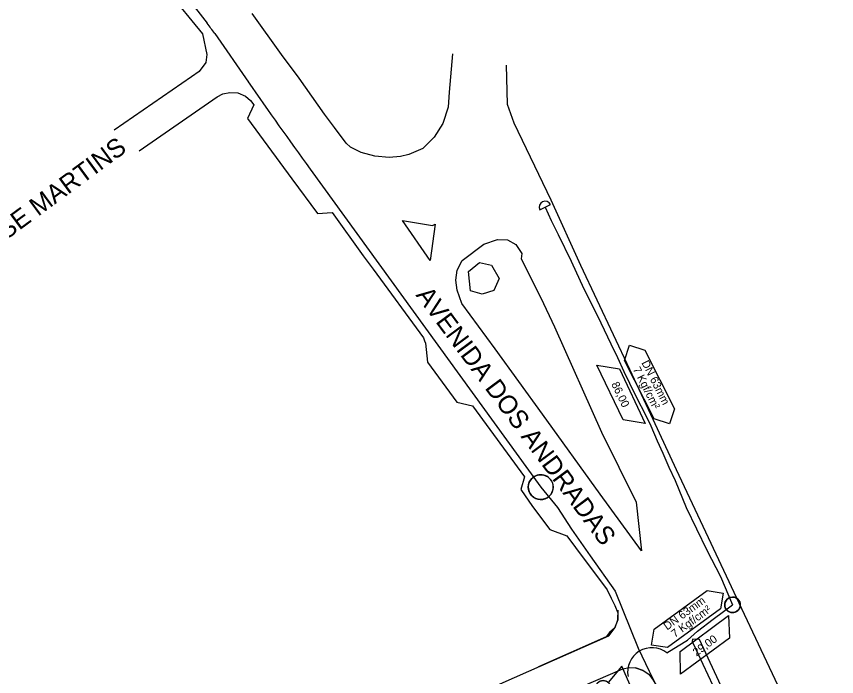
# Model space of a CAD drawing. Extents: x 656692 to 673945, y 7585994 to 7599066.
# Drawn here: x 669344.7 to 669663.5, y 7595890.6 to 7596147.3 of the extents above; entities that cross this region are included whole.
import ezdxf

# ---------------------------------------------------------------- set-up
doc = ezdxf.new("R2010")
doc.units = 0
for name, color, linetype in [('LOGRADOURO', 7, 'Continuous'), ('LOGRADOURO_TEXTO', 7, 'Continuous'), ('MEIO FIO', 7, 'Continuous'), ('SIMBOLO', 7, 'Continuous'), ('TEXTO', 7, 'Continuous'), ('TUBO_PEAD_GN_125', 7, 'Continuous'), ('TUBO_PEAD_GN_63', 7, 'Continuous'), ('VALVULA_PEAD_63', 7, 'Continuous')]:
    doc.layers.add(name, color=color, linetype=linetype)

# ---------------------------------------------------------------- blocks, each defined once
blk = doc.blocks.new('INTERLIGACAO_9')
at = {"layer": 'SIMBOLO'}
blk.add_circle((0, 0), 4.19, dxfattribs=at)
for start, end in [(0, 180), (180, 0)]:
    blk.add_arc((0, 0), 4.19, start, end, dxfattribs=at)
blk = doc.blocks.new('VALVULA_PEAD_DN_16')
at = {"layer": 'VALVULA_PEAD_63'}
for points in [[(-0.0374, 0.0187), (-0.1395, 0.0698), (-0.1395, -0.0698), (-0.0374, -0.0187)], [(-0.0374, -0.0187), (-0.1395, -0.0698), (-0.1395, 0.0698), (-0.0374, 0.0187)], [(0.0374, -0.0187), (0.1395, -0.0698), (0.1395, 0.0698), (0.0374, 0.0187)], [(0.0374, -0.0187), (0.1395, -0.0698), (0.1395, 0.0698), (0.0374, 0.0187)]]:
    blk.add_lwpolyline(points, dxfattribs=at)
blk.add_circle((0, 0), 0.0419, dxfattribs=at)
for start, end in [(90, 270), (153.4349, 206.5651), (270, 90), (333.4349, 26.5651)]:
    blk.add_arc((0, 0), 0.0419, start, end, dxfattribs=at)
blk = doc.blocks.new('INTERLIGACAO_12')
at = {"layer": 'SIMBOLO'}
blk.add_circle((0, 0), 4.19, dxfattribs=at)
for start, end in [(0, 180), (180, 0)]:
    blk.add_arc((0, 0), 4.19, start, end, dxfattribs=at)

msp = doc.modelspace()

# ---------------------------------------------------------------- linework, layer by layer
at = {"layer": 'LOGRADOURO'}
msp.add_line((669588.36, 7595892.97), (669585.35, 7595894.02), dxfattribs=at)
for points in [[(669403.4, 7596157.23), (669416.98, 7596140.49), (669418.75, 7596132.42), (669418.35, 7596129.3), (669415.73, 7596125.88), (669412.71, 7596123.73), (669382.74, 7596102.97)], [(669514.24, 7596132.7), (669512.92, 7596117.74), (669512.56, 7596111.95), (669510.49, 7596105.58), (669507.03, 7596100.34), (669502.7, 7596095.96), (669497.23, 7596093.53), (669494.06, 7596092.8), (669489.66, 7596092.37), (669484.06, 7596092.87), (669478.77, 7596094.33), (669474.63, 7596096.47), (669472.92, 7596098.02), (669468.37, 7596104.02), (669464.44, 7596109.21), (669454.67, 7596123.26), (669447.71, 7596132.4), (669436.32, 7596148.42)], [(669535.04, 7596128.35), (669535.5, 7596113.18), (669538, 7596105.82), (669552.44, 7596075.95), (669564.02, 7596050.57), (669582.96, 7596010.06), (669592.14, 7595990.61), (669601.2, 7595971.12), (669613.6, 7595944.63), (669626.5, 7595917.1), (669642.76, 7595882.69)], [(669392.44, 7596095.01), (669422.69, 7596116.02), (669424.99, 7596117.2), (669427.63, 7596117.73), (669430.74, 7596117.48), (669433.8, 7596116.26), (669435.71, 7596114.53), (669436.94, 7596112.83), (669434.56, 7596107.61), (669451.82, 7596084.16), (669461.78, 7596070.56), (669467.47, 7596071.04), (669479.52, 7596054.19), (669483.37, 7596049), (669502.91, 7596022.26), (669503.37, 7596021.1), (669503.73, 7596020.16), (669504.5, 7596012.81), (669515.96, 7595997.29), (669521.95, 7595995.87), (669542.18, 7595968.2), (669540.78, 7595963.27), (669545.35, 7595956.74), (669552.02, 7595947.8), (669558.7, 7595945.31), (669562.04, 7595940.74), (669574.36, 7595924.25), (669575.86, 7595921.11), (669577.33, 7595918.21), (669578.54, 7595915.31), (669578.46, 7595912.59), (669577.23, 7595909.39), (669575.24, 7595907.72), (669573.97, 7595905.98), (669547.68, 7595894.4)], [(669321.54, 7595794.23), (669359.27, 7595810.97), (669367.95, 7595814.75), (669399.74, 7595828.85), (669417.79, 7595836.75), (669442.46, 7595847.64), (669450.75, 7595844.67), (669458.2, 7595847.94), (669465.54, 7595851.19), (669466.64, 7595858.35), (669468.76, 7595859.3), (669477.05, 7595862.95), (669507.28, 7595876.53), (669538.25, 7595890.25), (669575.02, 7595906.45), (669577.47, 7595909.7), (669578.46, 7595912.59), (669578.58, 7595916.4)], [(669553.79, 7595882.06), (669580.42, 7595893.61), (669582.82, 7595894.1), (669585.35, 7595894.02), (669588.34, 7595892.98), (669590.53, 7595891.47), (669592.25, 7595889.23), (669594.49, 7595885.22), (669611.97, 7595846.58), (669622.46, 7595823.54), (669633.74, 7595799.1), (669648.11, 7595768.42), (669649.11, 7595765.62), (669649.81, 7595762.99), (669649.9, 7595759.85), (669649.5, 7595757.16), (669648.42, 7595754.65), (669646.35, 7595751.78), (669644.89, 7595750.78), (669637.86, 7595747.18), (669632.34, 7595749.1), (669607.54, 7595737.68)]]:
    msp.add_lwpolyline(points, dxfattribs=at)
for points in [[(669531.69, 7596060.54), (669535.62, 7596060.32), (669538.88, 7596058.51), (669541.16, 7596055.01), (669540.94, 7596053.01), (669548.49, 7596037.81), (669553.83, 7596026.5), (669572.14, 7595985.59), (669585.66, 7595958.43), (669587.64, 7595939.52), (669571.56, 7595961.47), (669549.19, 7595992.6), (669530.85, 7596017.95), (669517.88, 7596035.69), (669516.08, 7596040.83), (669515.51, 7596044.68), (669516.04, 7596048.65), (669518.01, 7596052.4), (669526.33, 7596058.74)], [(669521.16, 7596040.51), (669520.43, 7596048.09), (669524.74, 7596051.57), (669529.31, 7596050.53), (669532.32, 7596045.33), (669530.32, 7596040.73), (669525.72, 7596039.21)], [(669607.45, 7595905.13), (669607.4, 7595904.23), (669607.57, 7595903.69), (669619.3, 7595878.82), (669646.8, 7595819.29), (669647.05, 7595819.15), (669660.73, 7595789.07), (669663.51, 7595790.14), (669649.55, 7595820.32), (669621.14, 7595881.57), (669610.2, 7595905.02)]]:
    msp.add_lwpolyline(points, close=True, dxfattribs=at)
at = {"layer": 'MEIO FIO'}
msp.add_lwpolyline([(669506.49, 7596065.93), (669507.48, 7596066.45), (669505.51, 7596052.33), (669494.81, 7596067.85)], close=True, dxfattribs=at)
at = {"layer": 'SIMBOLO'}
for points in [[(669582.99, 7596019.46), (669588.93, 7596017.51), (669600.46, 7595994.73), (669598.51, 7595988.78), (669592.57, 7595990.73), (669581.04, 7596013.52), (669582.99, 7596019.46)], [(669591.59, 7595902.82), (669592.57, 7595909), (669613.22, 7595924.02), (669619.4, 7595923.04), (669618.43, 7595916.86), (669597.77, 7595901.84), (669591.59, 7595902.82)]]:
    msp.add_lwpolyline(points, dxfattribs=at)
at = {"layer": 'TEXTO'}
for points in [[(669579.06, 7596010.21), (669589.16, 7595988.99), (669580.51, 7595990.34), (669570.34, 7596011.69), (669579.06, 7596010.21)], [(669602.64, 7595900.34), (669621.55, 7595914.3), (669621.87, 7595905.55), (669602.84, 7595891.5), (669602.64, 7595900.34)]]:
    msp.add_lwpolyline(points, dxfattribs=at)
at = {"layer": 'TUBO_PEAD_GN_125'}
for p, q in [((669395.93, 7596174.39), (669418.86, 7596144.6)), ((669421.78, 7596140.6), (669434.86, 7596121.75)), ((669458.87, 7596087.89), (669548.51, 7595964.23))]:
    msp.add_line(p, q, dxfattribs=at)
msp.add_lwpolyline([(669548.51, 7595964.23), (669555.08, 7595956.26), (669560.48, 7595947.9), (669567.69, 7595937.57), (669577.47, 7595923.79), (669586.34, 7595901.62), (669590.7, 7595892.69), (669596.78, 7595880.52)], dxfattribs=at)
for centre, radius, start, end in [((669339.51, 7596083.53), 100.12, 34.7502, 37.5824), ((671080.16, 7597263.15), 2002.45, 214.75024, 215.9378)]:
    msp.add_arc(centre, radius, start, end, dxfattribs=at)
at = {"layer": 'TUBO_PEAD_GN_63'}
msp.add_line((669548.18, 7596072.05), (669552.32, 7596074.09), dxfattribs=at)
for points in [[(669550.25, 7596073.07), (669552.51, 7596067.84), (669555.34, 7596062.43), (669560.34, 7596052.06), (669565.27, 7596041.36), (669570.53, 7596030.77), (669573.16, 7596025.35), (669575.75, 7596019.99), (669578.33, 7596014.64), (669580.86, 7596009.25), (669583.07, 7596004.63), (669585.82, 7595998.78), (669589.08, 7595992.57), (669591.32, 7595988.02), (669593.72, 7595982.25), (669595.97, 7595977.38), (669598.31, 7595972.01), (669600.7, 7595966.76), (669605.1, 7595956.31), (669613.04, 7595939.78), (669618.36, 7595929.47), (669623.05, 7595918.47)], [(669597.57, 7595899.82), (669601.87, 7595902.47), (669605.56, 7595904.74), (669609.47, 7595908.17), (669615.54, 7595912.91), (669623.05, 7595918.47)]]:
    msp.add_lwpolyline(points, dxfattribs=at)
for centre, radius, start, end in [((669550.25, 7596073.07), 2.31, 26.2909, 206.1425), ((669591.75, 7595892.33), 9.48, 52.1284, 190.7931)]:
    msp.add_arc(centre, radius, start, end, dxfattribs=at)

# ---------------------------------------------------------------- block references
at = {"layer": 'SIMBOLO'}
for name, p, xscale, yscale, rotation in [('INTERLIGACAO_12', (669548.51, 7595964.23), 1.15343669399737, 1.15343669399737, 166.3322212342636), ('INTERLIGACAO_9', (669623.05, 7595918.47), 0.7229249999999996, 0.7229249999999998, 166.312122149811)]:
    msp.add_blockref(name, p, dxfattribs=dict(at, xscale=xscale, yscale=yscale, rotation=rotation))
at = {"layer": 'VALVULA_PEAD_63', "xscale": 72.29249999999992, "yscale": 72.29249999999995, "rotation": 23.827974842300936}
msp.add_blockref('VALVULA_PEAD_DN_16', (669572.79, 7595885.98), dxfattribs=at)

# ---------------------------------------------------------------- texts
at = {"layer": 'LOGRADOURO_TEXTO'}
for s, rotation, p in [('RUA ANTONIO JOSE MARTINS', 36.358, (669274.74, 7596011.61)), ('AVENIDA DOS ANDRADAS', 306.5847, (669499.75, 7596038.85))]:
    msp.add_text(s, height=7.2, rotation=rotation, dxfattribs=at).set_placement(p)
at = {"layer": 'TEXTO'}
for s, rotation, p in [('7 Kgf/cm²', 296.8427, (669584.24, 7596010.08)), ('DN 63mm', 296.8427, (669587.59, 7596012.59)), ('86,00', 295.4645, (669575.86, 7596004.31)), ('DN 63mm', 36.0201, (669597.64, 7595908.46)), ('7 Kgf/cm²', 36.0201, (669600.66, 7595905.55)), ('29,00', 36.4427, (669609.04, 7595898.33))]:
    msp.add_text(s, height=3.113, rotation=rotation, dxfattribs=at).set_placement(p)

doc.saveas('drawing.dxf')
